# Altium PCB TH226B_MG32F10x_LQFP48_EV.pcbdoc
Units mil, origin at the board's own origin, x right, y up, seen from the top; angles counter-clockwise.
Board outline 3031.5 x 2165.35 mil, 2 copper layers (Top Layer, Bottom Layer); 46 components, 52 nets, 219 pads, 112 vias.
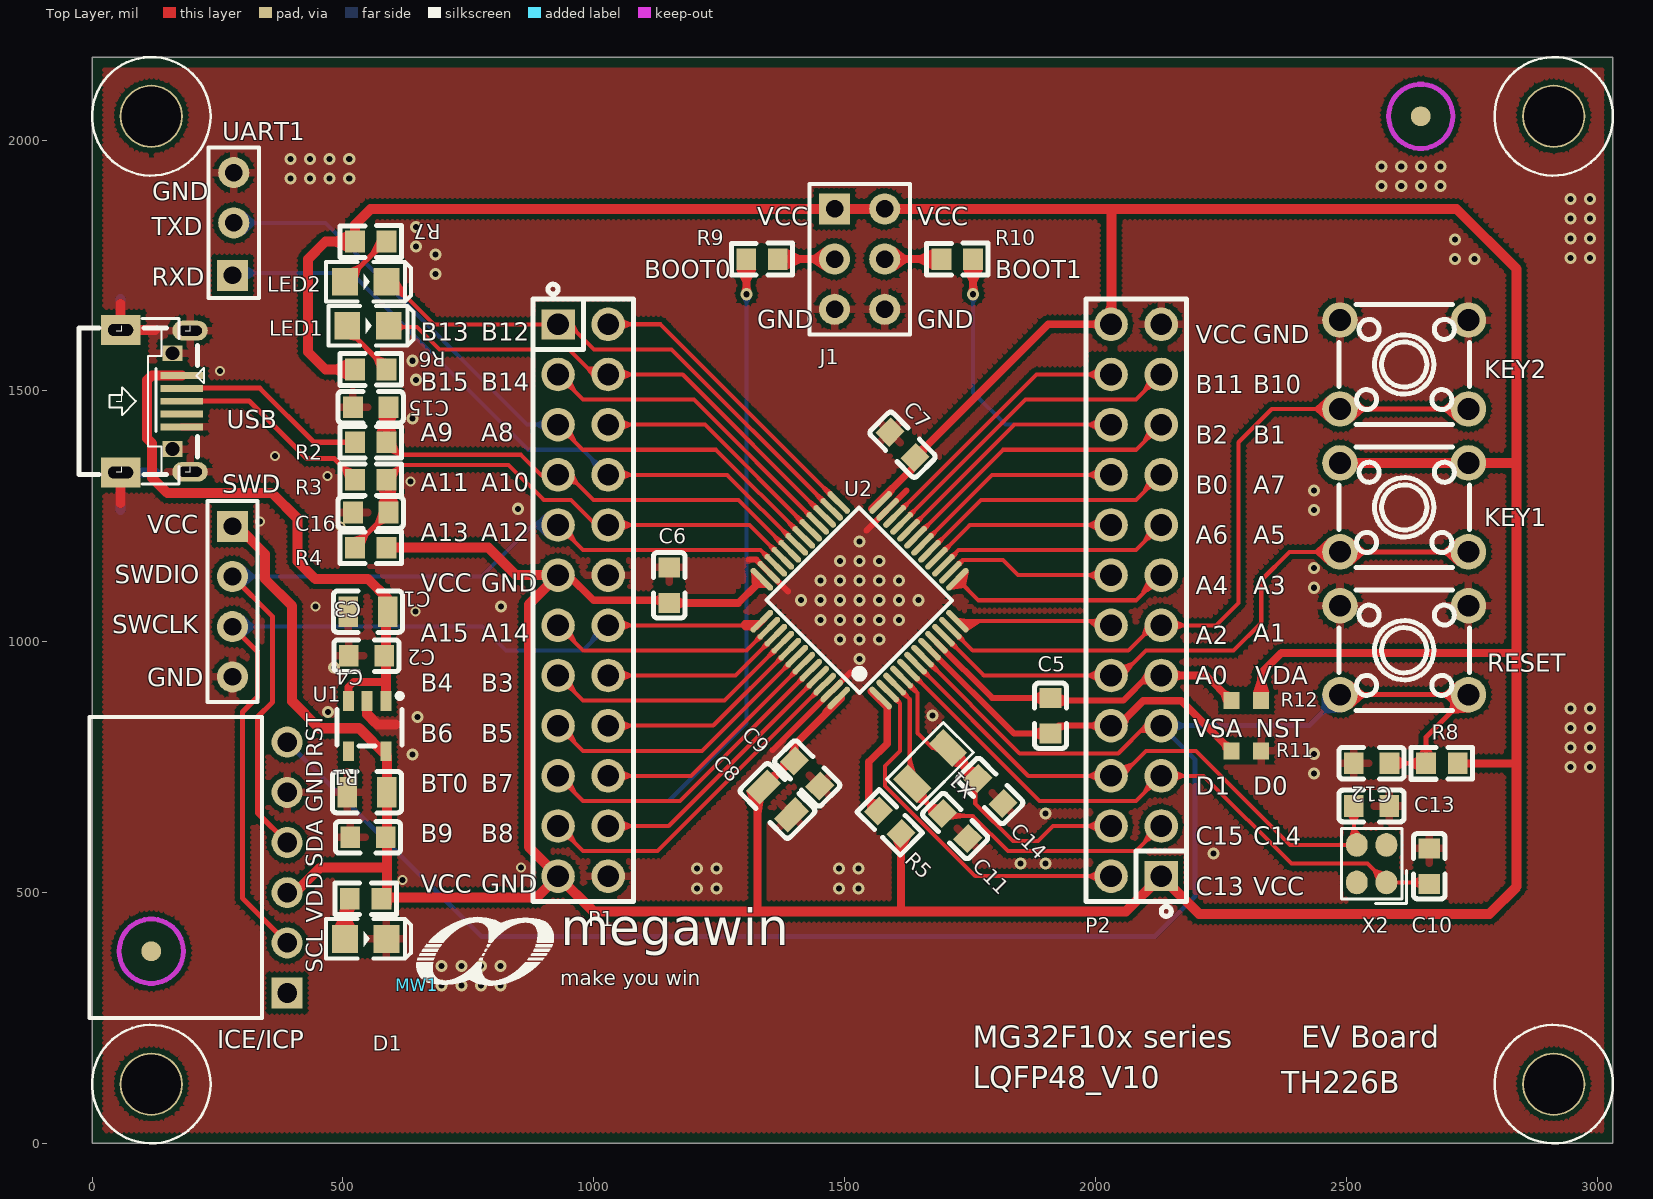
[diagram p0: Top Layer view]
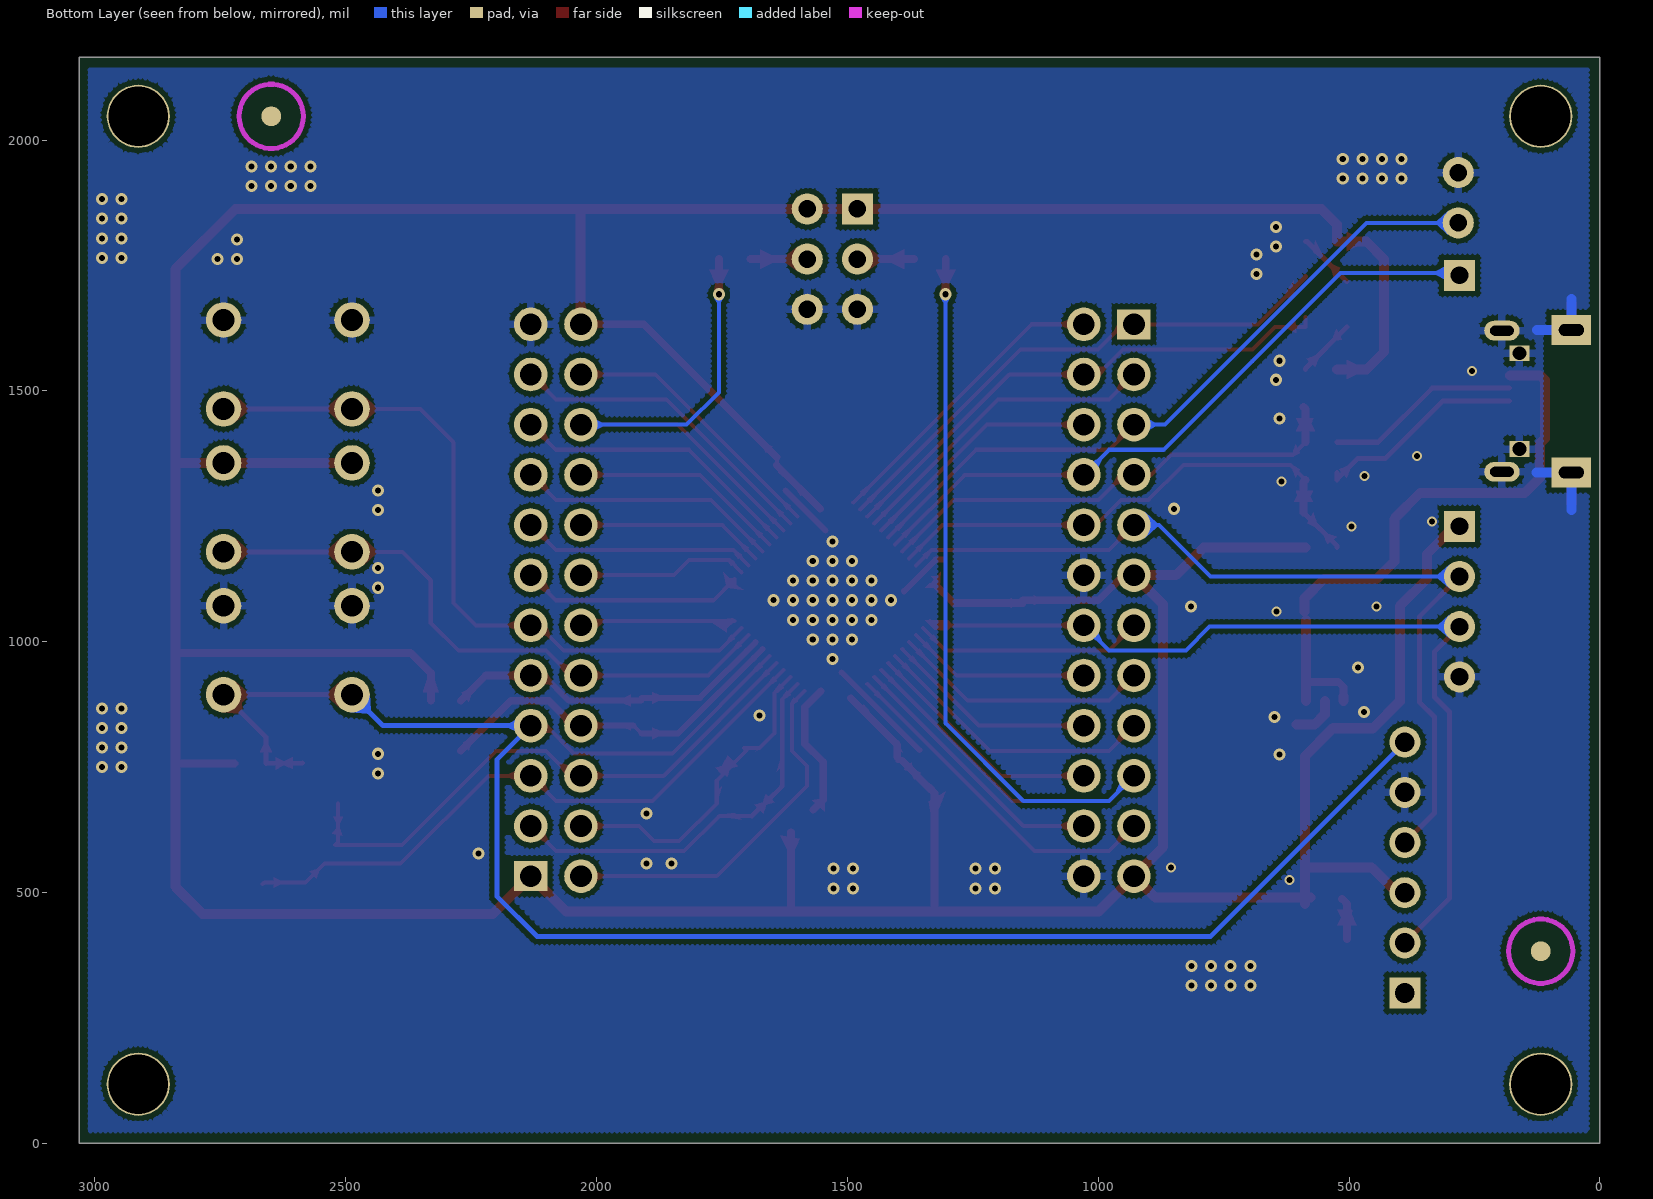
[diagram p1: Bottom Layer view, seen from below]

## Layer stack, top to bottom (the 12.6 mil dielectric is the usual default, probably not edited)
Top Layer: signal copper 1.4
Dielectric: dielectric 12.6, FR-4, Dk 4.8
Bottom Layer: signal copper 1.4

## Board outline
0,0 3031.5,0 3031.5,2165.35 0,2165.35

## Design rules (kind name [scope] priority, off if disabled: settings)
Clearance Clearance_1 [All] p1 off: gap=10
Clearance 6 [All] p2: gap=6
PolygonConnect via [isvia] p1: connectstyle=Direct reliefconductorwidth=10 reliefentries=4 polygonreliefangle="90 Angle"
PolygonConnect PolygonConnect_1 [All] p2: connectstyle=Relief reliefconductorwidth=15 reliefentries=4 polygonreliefangle="90 Angle"
RoomDefinition TH226B_MG32F10x_LQFP48_EV_V10 [InComponentClass('TH226B_MG32F10x_LQFP48_EV_V10')] p1: confinementstyle=ConfineIn formatcopy=TRUE lockcomponents=FALSE outline -125,-57 3071,-57 3071,2222 -125,2222
RoutingVias [All] p1: holewidth=28 width=50 viastyle="Through Hole" minholewidth=28 minwidth=50 maxholewidth=28 maxwidth=50
SilkscreenOverComponentPads SilkToSolderMaskClearance [IsPad] p1: minsilkscreentomaskgap=10
SolderMaskExpansion [All] p1: expansion=4
Width [All] p1: maxlimit=78.74 minlimit=5 preferedwidth=10
27 further rules are at their usual default settings.

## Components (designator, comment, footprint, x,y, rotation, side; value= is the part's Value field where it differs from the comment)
C1 "10uF" C0805 550,1059.78 r180 top
C2 "0.1uF" C0603 547.24,971.99 r180 top
C3 "10uF" C0805 548.3,700 r180 top
C4 "0.1uF" C0603 550,610 r180 top
C5 "0.1uF" C0603 1910.44,852.56 r270 top
C6 "0.1uF" C0603 1150.44,1112.56 r90 top
C7 "0.1uF" C0603 1615.44,1392.56 r135 top
C8 "10uF" C0805 1366.3,682.56 r315 top
C9 "0.1uF" C0603 1425.44,737.56 r315 top
C10 "20pF" C0603 2665.4,552.56 r90 top
C11 "12pF" C0603 1720.4,632.56 r315 top
C12 "0.1uF" C0603 2550.43,757.99 r180 top
C13 "20pF" C0603 2550.4,672.56 r0 top
C14 "12pF" C0603 1790.4,702.56 r315 top
C15 "20pF" C0603 555.44,1467.56 r0 top
C16 "20pF" C0603 555.44,1257.56 r0 top
D1 "" LED0805_RED 545.44,407.56 r0 top
ICE/ICP "" PS6P254F_90 388.94,299.78 r90 top locked (schematic designator J8)
J1 "CON3X2" HDR-M-2.54_2X3 1480,1862.56 r270 top
KEY1 "SW-PB4" KEY-TH_4P-L6.0-W6.0-P4.50-LS6.5 2615.43,1267.78 r180 top
KEY2 "SW-PB4" KEY-TH_4P-L6.0-W6.0-P4.50-LS6.5 2615.44,1552.56 r180 top
LED1 "" LED0805_RED 550,1630 r0 top
LED2 "" LED0805_GREEN 545.43,1717.56 r0 top
MW1 "MW-A4" MEGAWIN_3.4 648.48,315.01 r0 top (schematic designator IMPORTED_IMAGE)
P1 "CON12X2" HDR-TH_24P-P2.54-V-R2-C12-S2.54 978.87,1082.66 r270 top
P2 "CON12X2" HDR-TH_24P-P2.54-V-R2-C12-S2.54 2081.17,1082.66 r90 top
R1 "4.7k" R0603 545.4,487.56 r180 top
R2 "33" R0603 555.44,1397.56 r0 top
R3 "33" R0603 555.43,1322.56 r0 top
R4 "1.5k" R0603 555.44,1187.56 r0 top
R5 "0" R0603 1590,640 r135 top
R6 "1.5k" R0603 555.5,1542.56 r0 top
R7 "10k" R0603 555.5,1797.56 r0 top
R8 "10k" R0603 2690.44,757.56 r180 top
R9 "10k" R0603 1335.44,1762.56 r0 top
R10 "10k" R0603 1724.57,1762.56 r0 top
R11 "0" R0603-1 2300.44,782.56 r180 top
R12 "0" R0603-1 2300.44,882.56 r180 top
RESET "SW-PB4" KEY-TH_4P-L6.0-W6.0-P4.50-LS6.5 2615.43,982.99 r180 top
SWD "CON4" HDR-M-2.54_1X4 280,1080 r270 top
U1 "SPX3819M5-L-3-3" SOT-23-5_L3.0-W1.7-P0.95-LS2.8-TL 548.36,831.95 r180 top
U2 "MG32F10x" LQFP-48_L7.0-W7.0-P0.50-LS9.0-BL 1530,1082.68 r45 top
UART1 "CON3" HDR-M-2.54_1X3 282.5,1834.9 r90 top (schematic designator UART)
USB "MICRO_USB" USB5-micro_B-建倚MRUSB-5B-D17xx- 167.96,1479.36 r270 top
X1 "32.768MHz" OSC-SMD_L3.2-W1.5 1670.44,752.56 r45 top
X2 "12MHz" OSC-SMD_4P-L2.5-W2.0-BL 2550.44,557.56 r90 top

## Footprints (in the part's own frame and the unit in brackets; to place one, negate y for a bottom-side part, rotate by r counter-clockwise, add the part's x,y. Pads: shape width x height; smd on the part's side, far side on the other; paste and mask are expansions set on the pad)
C0603 [mm]
  rect 1x1.1 smd: 1(-0.9,0) 2(0.9,0)
  silkscreen extent -1.65,-0.8 1.65,0.8
C0805 [mm]
  rect 1x1.55 smd: 1(-1,0) 2(1,0)
  silkscreen extent -1.75,-1.04 1.75,1.04
HDR-M-2.54_1X3 [mil]
  rect 62x62 hole 35: 1(-104.9,2.5)
  round 62 hole 35: 2(0,0) 3(100,0)
  silkscreen extent -150,-50 150,50
HDR-M-2.54_1X4 [mil]
  rect 62x62 hole 35: 1(-150,0)
  round 62 hole 35: 2(-50,0) 3(50,0) 4(150,0)
  silkscreen extent -200,-50 200,50
HDR-M-2.54_2X3 [mil]
  rect 62x62 hole 35: 1(0,0)
  round 62 hole 35: 2(0,100) 3(100,0) 4(100,100) 5(200,0) 6(200,100)
  silkscreen extent -50,-50 250,150
HDR-TH_24P-P2.54-V-R2-C12-S2.54 [mm]
  rect 1.524x1.7 hole 1.1: 1(-13.97,-1.27)
  round 1.7 hole 1.1: 2(-13.97,1.27) 3(-11.43,-1.27) 4(-11.43,1.27) 5(-8.89,-1.27) 6(-8.89,1.27) 7(-6.35,-1.27) 8(-6.35,1.27) 9(-3.81,-1.27) 10(-3.81,1.27) 11(-1.27,-1.27) 12(-1.27,1.27) 13(1.27,-1.27) 14(1.27,1.27) 15(3.81,-1.27) 16(3.81,1.27) 17(6.35,-1.27) 18(6.35,1.27) 19(8.89,-1.27) 20(8.89,1.27) 21(11.43,-1.27) 22(11.43,1.27) 23(13.97,-1.27) 24(13.97,1.27)
  silkscreen extent -16,-2.54 15.24,2.54
KEY-TH_4P-L6.0-W6.0-P4.50-LS6.5 [mm]
  round 1.8 hole 1.1: 1(-3.251,-2.25) 2(3.251,-2.25) 3(3.251,2.25) 4(-3.251,2.25)
  silkscreen extent -3.3,-3.05 3.3,3.05
LED0805_GREEN [mil]
  rect 51.2x55.1 smd: 1(-41.35,0) 2(41.35,0)
  silkscreen extent -79,-39 91,39
LED0805_RED [mil]
  rect 51.2x55.1 smd: 1(-41.35,0) 2(41.35,0)
  silkscreen extent -79,-39 91,39
LQFP-48_L7.0-W7.0-P0.50-LS9.0-BL [mm]
  oval 0.3x1.5 smd: 1(-2.75,-4.25) 2(-2.25,-4.25) 3(-1.75,-4.25) 4(-1.25,-4.25) 5(-0.75,-4.25) 6(-0.25,-4.25) 7(0.25,-4.25) 8(0.75,-4.25) 9(1.25,-4.25) 10(1.75,-4.25) 11(2.25,-4.25) 12(2.75,-4.25) 25(2.75,4.25) 26(2.25,4.25) 27(1.75,4.25) 28(1.25,4.25) 29(0.75,4.25) 30(0.25,4.25) 31(-0.25,4.25) 32(-0.75,4.25) 33(-1.25,4.25) 34(-1.75,4.25) 35(-2.25,4.25) 36(-2.75,4.25)
  oval 1.5x0.3 smd: 13(4.25,-2.75) 14(4.25,-2.25) 15(4.25,-1.75) 16(4.25,-1.25) 17(4.25,-0.75) 18(4.25,-0.25) 19(4.25,0.25) 20(4.25,0.75) 21(4.25,1.25) 22(4.25,1.75) 23(4.25,2.25) 24(4.25,2.75) 37(-4.25,2.75) 38(-4.25,2.25) 39(-4.25,1.75) 40(-4.25,1.25) 41(-4.25,0.75) 42(-4.25,0.25) 43(-4.25,-0.25) 44(-4.25,-0.75) 45(-4.25,-1.25) 46(-4.25,-1.75) 47(-4.25,-2.25) 48(-4.25,-2.75)
  silkscreen extent -3.33,-3.31 3.3,3.34
MEGAWIN_3.4 [mil]
  silkscreen extent -2,0 272,135
OSC-SMD_4P-L2.5-W2.0-BL [mm]
  oval 1.2x1.1 smd: 1(-0.95,-0.75) 2(0.95,-0.75) 3(0.95,0.75) 4(-0.95,0.75)
  silkscreen extent -2.01,-1.76 1.78,1.53
OSC-SMD_L3.2-W1.5 [mm]
  rect 1.05x1.7 smd: 1(-1.275,0) 2(1.275,0)
  silkscreen extent -2.03,-1.08 2.03,1.08
PS6P254F_90 [mil]
  rect 62x62 hole 39.37: 1(0,0)
  round 62 hole 39.37: 2(100,0) 3(200,0) 4(300,0) 5(400,0) 6(500,0)
  silkscreen extent -50,50 550,394
R0603 [mm]
  rect 1x1.1 smd: 1(-0.8,0) 2(0.8,0)
  silkscreen extent -1.55,-0.8 1.55,0.81
R0603-1 [mil]
  rect 31.75x34.02 smd: 1(-29.66,0) 2(29.66,0)
SOT-23-5_L3.0-W1.7-P0.95-LS2.8-TL [mm]
  rect 0.55x1 smd: 1(-0.95,-1.271) 2(0,-1.271) 3(0.95,-1.271) 4(0.95,1.271) 5(-0.95,1.271)
  silkscreen extent -1.78,-1.65 1.52,1.02
USB5-micro_B-建倚MRUSB-5B-D17xx- [mm]
  rect 0.35x2.159 smd: 1(-1.3,0.279) 2(-0.65,0.279) 3(0,0.279) 4(0.65,0.279) 5(1.3,0.279)
  rect 0.8x1 hole 0.7: 5(-2.425,-0.19) 5(2.425,-0.19)
  oval 1x1.8 hole 0.5 slot 1.2 at 90 deg: 6(3.576,0.697) 9(-3.574,0.697)
  rect 1.5x2 hole 0.6 slot 1.27 at 90 deg: 7(3.607,-2.819) 8(-3.607,-2.819)
  silkscreen extent -4.19,-4.92 4.19,1.4, body extent -4,-5.61 4,-0.01, height 2.8

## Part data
C1 C2 C3 C4 C5 C6 C7 C8 C9 C10 C11 C12 C13 C14 C15 C16: library part CAP, "Capacitor"
D1 LED1 LED2: library part LED_SC
ICE/ICP: library part CON6, "Connector"
MW1: library part MW_A4
R1 R2 R3 R4 R5 R6 R7 R8 R9 R10 R11 R12: library part RES1
SWD UART1: "Connector"
U1: library part IC5_SPX3819M5-L-3-3
U2: library part IC48_MG32F10x
USB: library part USB_Micro
X1: library part XTAL, "Crystal"
X2: library part X3P_1, "Crystal"

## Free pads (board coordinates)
  round 125.98 hole 118.11: 0(118.11,118.12) 0(118.12,2047.25) 0(2913.38,118.11) 0(2913.39,2047.24)
  round 39.37 smd mask+39.37: 0(118.11,383.12) 0(2648.39,2047.24)
  round 39.37 smd far side mask+39.37: 0(118.11,383.12) 0(2648.39,2047.24)

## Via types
v1: diameter 24, hole 12, Top Layer to Bottom Layer, tented both sides, 102 vias
v2: diameter 20, hole 12, Top Layer to Bottom Layer, tented both sides, 10 vias

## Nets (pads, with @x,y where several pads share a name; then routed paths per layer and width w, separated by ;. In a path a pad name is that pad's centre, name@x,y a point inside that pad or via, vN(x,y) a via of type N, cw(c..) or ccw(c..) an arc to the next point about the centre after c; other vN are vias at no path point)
BOOT0: P1.19 R9.1 U2.44 | length 2018.2
  Top Layer w8.19: P1.19 978.97,682.56 1171.67,682.56 U2.44
  Top Layer w15.75: R9.1 v1(1304.57,1692.56)
  Bottom Layer w8.19: P1.19 978.97,682.56 1149.57,682.56 1304.57,837.56 v1(1304.57,1692.56)
D+: R3.1 USB.3 | length 444.8
  Top Layer w10: USB.3@180.2,1479.8 313.23,1479.8 428.03,1365 483.03,1365 R3.1@515.72,1332.31 ; 500.47,1347.56 R3.1@523.97,1324.06 ; R3.1 R3.1@523.97,1337.56
D-: R2.1 USB.2 | length 388.4
  Top Layer w10: USB.2@180.2,1505.4 334.6,1505.4 442.44,1397.56 R2.1
GND_POWER: C1.2 C2.2 C3.2 C4.2 C6.2 C7.2 C8.2 C9.2 C10.2 C11.2 C12.2 C13.2 C14.2 C15.1 C16.1 D1.2 ICE/ICP.5 J1.5 J1.6 KEY2.1 KEY2.2 P1.12 P1.24 P2.23 R11.1 RESET.1 RESET.2 SWD.4 U1.2 U2.23 U2.35 U2.47 UART1.3 USB.5 USB.6 USB.7 USB.8 USB.9 | length 981.2
  Top Layer w12: 1308.94,1163.46 1323.96,1163.46 1386.82,1100.58 ; 1356.79,784.23 1511.73,939.12 ; 1543.41,1221.37 1623.09,1301.02
  Top Layer w20: 56.96,1276.98 USB.7 ; 56.96,1673.02 USB.8 125.3,1621.36 ; U1.2 548.37,855.36 568.73,835 605,835
  Bottom Layer w20: 56.96,1263.02 USB.7 126.3,1337.36 ; 56.96,1682.82 USB.8 125.3,1621.36
  other v1: 696.96,314.78 736.06,314.78 775.15,314.78 814.25,314.78 696.96,353.87 736.06,353.87 775.15,353.87 814.25,353.87 1205.44,508.47 1244.53,508.47 1488.63,508.47 1527.72,508.47 1205.44,547.56 1244.53,547.56 1488.63,547.56 1527.72,547.56 1850.44,557.56 1900.44,557.56 2235.46,577.56 1900.44,657.56 2435.46,737.56 2946.57,749.9 2985.67,749.9 638.94,775 2435.46,776.66 2946.57,788.99 2985.67,788.99 2946.57,828.09 2985.67,828.09 648.94,850 1675.46,852.56 470,860 2946.57,867.18 2985.67,867.18 482.28,948.37 1530,965.41 1490.91,1004.5 1530,1004.5 1569.09,1004.5 1451.82,1043.59 1490.91,1043.59 1530,1043.59 1569.09,1043.59 1608.19,1043.59 815,1069.78 1412.73,1082.68 1451.82,1082.68 1490.91,1082.68 1530,1082.68 1569.09,1082.68 1608.19,1082.68 1647.28,1082.68 2435.46,1107.56 1451.82,1121.77 1490.91,1121.77 1530,1121.77 1569.09,1121.77 1608.19,1121.77 2435.46,1146.66 1490.91,1160.86 1530,1160.86 1569.09,1160.86 1530,1199.95 2435.46,1262.56 848.94,1265 2435.46,1301.66 638.94,1445 645.46,1522.12 638.94,1560 684.55,1732.56 2716.37,1762.56 2755.46,1762.56 2946.57,1764.9 2985.67,1764.9 684.55,1771.66 645.46,1787.56 2716.37,1801.66 2946.57,1803.99 2985.67,1803.99 645.46,1826.66 2946.57,1843.09 2985.67,1843.09 2946.57,1882.18 2985.67,1882.18 2570.44,1908.46 2609.53,1908.46 2648.63,1908.46 2687.72,1908.46 395.44,1923.46 434.53,1923.46 473.63,1923.46 512.72,1923.46 2570.44,1947.56 2609.53,1947.56 2648.63,1947.56 2687.72,1947.56 395.44,1962.56 434.53,1962.56 473.63,1962.56 512.72,1962.56
  other v2: 618.94,525 855,549.78 645,1059.78 445,1069.78 495,1229.78 335,1239.78 635,1319.78 468.94,1330 365,1369.78 255,1539.78
NetD1_1: D1.1 R1.2 | length 84.1
  Top Layer w15.75: D1.1 504.07,477.66 R1.2
NetJ1_3: J1.3 R9.2 | length 113
  Top Layer w15.75: R9.2 J1.3@1479.97,1762.56
NetJ1_4: J1.4 R10.1 | length 113.1
  Top Layer w15.75: J1.4@1579.97,1762.56 R10.1
NetLED1_1: LED1.1 R6.2 | length 119.3
  Top Layer w10: LED1.1@504.07,1627.56 586.97,1544.66 R6.2
NetLED2_1: LED2.1 R7.2 | length 116
  Top Layer w10: LED2.1 584.07,1797.56 R7.2
NRST: C12.1 ICE/ICP.6 P2.7 R8.2 RESET.3 RESET.4 U2.7 | length 4043.2
  Top Layer w8.19: U2.7@1655.27,971.36 1849.07,777.56 2045.47,777.56 2100.57,832.66 P2.7
  Top Layer w10: RESET.3 RESET.4 2658.97,809.86 R8.2 C12.1
  Bottom Layer w10: ICE/ICP.6 776.07,412.66 1888.87,412.66 ; 2098.87,412.66 1888.87,412.66 ; RESET.3 2425.67,832.66 P2.7 2198.87,764.96 2198.87,492.66 2118.87,412.66 1888.87,412.66
PA0: KEY1.3 KEY1.4 P2.10 U2.10 | length 1231.6
  Top Layer w8.19: U2.10 1777.47,932.66 P2.10 2050.57,932.66 2100.47,982.56 2275.47,982.56 2330.47,1037.56 2330.47,1122.56 2387.07,1179.16 KEY1.3
  Top Layer w10: KEY1.3 KEY1.4
PA1: KEY2.3 KEY2.4 P2.11 U2.11 | length 1437.6
  Top Layer w8.19: U2.11 1755.37,982.56 2065.47,982.56 2115.57,1032.66 P2.11 2240.57,1032.66 2285.47,1077.56 2285.47,1397.56 2351.37,1463.56 KEY2.3
  Top Layer w10: KEY2.3 KEY2.4
PA2: P2.12 U2.12 | length 309.8
  Top Layer w8.19: U2.12@1724.87,1040.96 2022.97,1040.96 P2.12
PA3: P2.13 U2.13 | length 444.4
  Top Layer w8.19: U2.13@1724.87,1124.46 1766.77,1082.56 2081.07,1082.56 P2.13
PA4: P2.14 U2.14 | length 342.6
  Top Layer w8.19: U2.14 1735.17,1162.56 1815.47,1162.56 1845.37,1132.66 P2.14
PA5: P2.15 U2.15 | length 467.4
  Top Layer w8.19: U2.15 1727.37,1182.56 2081.07,1182.56 P2.15
PA6: P2.16 U2.16 | length 375.6
  Top Layer w8.19: U2.16@1683.07,1166.16 1749.57,1232.66 P2.16
PA7: P2.17 U2.17 | length 525.2
  Top Layer w8.19: U2.17@1669.17,1180.06 1771.67,1282.56 2081.07,1282.56 P2.17
PA8: P1.6 U2.29 | length 491
  Top Layer w8.19: P1.6 1221.77,1432.66 U2.29
PA9: P1.5 U2.30 UART1.2 | length 1395.9
  Top Layer w8.19: P1.5 978.97,1382.56 1244.07,1382.56 U2.30
  Bottom Layer w8.19: UART1.2 465.1,1834.9 867.34,1432.66 P1.5
PA10: P1.8 U2.31 UART1.1 | length 1358.5
  Top Layer w8.19: P1.8 1266.07,1332.66 U2.31@1404.77,1194.06
  Bottom Layer w8.19: UART1.1@282.5,1734.9 517.23,1734.9 693.19,1558.94 ; 684.57,1567.56 869.57,1382.56 978.97,1382.56 P1.8
PA11: C15.2 P1.7 R2.2 U2.32 | length 1000.8
  Top Layer w8.19: P1.7@928.77,1332.66 895.07,1332.66 855.17,1372.56 611.97,1372.56 ; P1.7 949.47,1332.66 999.57,1282.56 1288.27,1282.56 U2.32@1390.77,1180.06 ; 611.97,1372.56 R2.2 611.93,1372.56
  Top Layer w15.75: R2.2 586.97,1463.66 C15.2
PA12: C16.2 P1.10 R3.2 R4.1 U2.33 | length 1065.1
  Top Layer w8.19: R3.2@601.97,1337.56 R3.2 616.97,1352.56 830.44,1352.56 900.44,1282.56 954.57,1282.56 1004.47,1232.66 P1.10 1310.37,1232.66 U2.33@1376.87,1166.16
  Top Layer w10: R4.1 523.97,1190.66 C16.2
  Top Layer w15.75: R3.2 590.87,1318.66 C16.2
PA13: ICE/ICP.4 P1.9 SWD.2 U2.34 | length 1768.9
  Top Layer w8.19: P1.9 978.97,1182.56 1332.67,1182.56 U2.34
  Top Layer w10: SWD.2 360,1050 360,880 330,850 330,658.73 ICE/ICP.4
  Bottom Layer w8.19: SWD.2@270,1130 SWD.2 776.21,1130 878.87,1232.66 P1.9@928.77,1232.66
PA14: ICE/ICP.2 P1.14 SWD.3 U2.37 | length 1794.6
  Top Layer w8.19: P1.14 1326.87,1032.66 U2.37@1335.17,1040.96
  Top Layer w10: SWD.3 330,980 330,890 300,860 300,488.73 ICE/ICP.2@385.76,402.97
  Bottom Layer w8.19: SWD.3 778.03,1030 825.47,982.56 978.67,982.56 P1.14@1028.77,1032.66
PA15: P1.13 U2.38 | length 459.3
  Top Layer w8.19: P1.13 978.97,982.56 1304.57,982.56 U2.38
PB0: P2.18 U2.18 | length 433.3
  Top Layer w8.19: U2.18@1655.27,1194.06 1793.97,1332.66 P2.18
PB1: P2.19 U2.19 | length 582.9
  Top Layer w8.19: U2.19 1815.97,1382.56 2081.07,1382.56 P2.19
PB2: P2.20 R10.2 U2.20 | length 1058.4
  Top Layer w8.19: U2.20 1838.27,1432.66 P2.20
  Top Layer w15.75: v1(1756.06,1692.56) R10.2
  Bottom Layer w8.19: v1(1756.06,1692.56) 1756.07,1496.96 1820.37,1432.66 P2.20
PB3: P1.16 U2.39 | length 367.4
  Top Layer w8.19: P1.16 1282.57,932.66 U2.39
PB4: P1.15 U2.40 | length 517
  Top Layer w8.19: P1.15 978.97,882.56 1260.27,882.56 U2.40
PB5: P1.18 U2.41 | length 425.1
  Top Layer w8.19: P1.18 1238.27,832.66 U2.41@1390.77,985.26
PB6: P1.17 U2.42 | length 574.9
  Top Layer w8.19: P1.17 978.97,782.56 1215.97,782.56 U2.42@1404.77,971.36
PB7: P1.20 U2.43 | length 482.9
  Top Layer w8.19: P1.20 1193.97,732.66 U2.43
PB8: P1.22 U2.45 | length 540.6
  Top Layer w8.19: P1.22 1149.57,632.66 U2.45
PB9: P1.21 U2.46 | length 690.3
  Top Layer w8.19: P1.21 978.97,582.56 1127.37,582.56 U2.46@1460.37,915.66
PB10: P2.21 U2.21 | length 640.6
  Top Layer w8.19: U2.21 1860.37,1482.56 2081.07,1482.56 P2.21
PB11: P2.22 U2.22 | length 548.8
  Top Layer w8.19: U2.22@1599.57,1249.76 1882.57,1532.66 P2.22
PB12: P1.2 U2.25 | length 606.5
  Top Layer w8.19: P1.2 1133.07,1632.66 U2.25
PB13: LED2.2 P1.1 U2.26 | length 1080.2
  Top Layer w8: 616.26,1698.12 681.72,1632.66 P1.1@928.77,1632.66
  Top Layer w8.19: P1.1 950.37,1632.66 1000.47,1582.56 1155.37,1582.56 U2.26@1474.37,1263.66
  Top Layer w10: LED2.2@586.82,1727.56 616.72,1697.66
PB14: LED1.2 P1.4 U2.27 | length 1050
  Top Layer w8.19: LED1.2@586.79,1647.56 586.79,1627.56 647.44,1627.56 692.44,1582.56 950.47,1582.56 1000.27,1532.66 P1.4@1028.77,1532.66 ; P1.4 1177.47,1532.66 U2.27@1460.37,1249.76
PB15: P1.3 U2.28 | length 640.6
  Top Layer w8.19: P1.3 978.97,1482.56 1199.67,1482.56 U2.28
PC13: P2.2 U2.2 | length 737.1
  Top Layer w8.19: U2.2@1585.67,901.76 1610.47,876.96 1610.47,782.56 1580.47,752.56 1580.47,712.56 1760.37,532.66 P2.2
PC14: C11.1 P2.3 U2.3 X1.1 | length 791.5
  Top Layer w8.19: U2.3 1629.97,885.26 X1.1@1629.97,712.06 ; C11.1@1690.37,652.66 1755.37,652.66 1825.47,582.56 2081.07,582.56 P2.3
  Top Layer w10: X1.1@1629.97,712.06 C11.1@1690.37,652.66
PC15: C14.1 P2.4 U2.4 X1.2 | length 648.5
  Top Layer w8.19: U2.4 1645.47,897.66 1645.47,817.56 ; 1646.07,816.96 1674.97,788.06 X1.2 1700.97,783.06 1760.37,723.56 1760.37,677.66 1835.47,602.56 1885.47,602.56 1915.47,632.56 P2.4
PD0: C10.1 P2.5 U2.5 X2.1 | length 1256
  Top Layer w8.19: U2.5 1888.37,682.56 2081.07,682.56 P2.5 2215.37,732.66 2390.47,557.56 2542.57,557.56 X2.1 2662.37,520.16 C10.1@2665.37,517.16
PD1: C13.1 P2.6 U2.6 X2.3 | length 1156
  Top Layer w8.19: U2.6 1866.07,732.66 P2.6 2050.57,732.66 2100.47,782.56 2200.47,782.56 2388.07,594.96 2520.87,594.96 2514.97,600.86 C13.1@2514.97,677.56
VBAT: R5.2 U2.1 | length 301.3
  Top Layer w8.19: 1548.17,684.86 R5.2@1568.17,664.86
  Top Layer w15: U2.1@1553.4,901.19 1585.04,869.52 1585,797.04 1548.17,760.26 1548.17,684.82 R5.2@1568.17,664.83
VCC: C3.1 C4.1 C6.1 C7.1 C8.1 C9.1 ICE/ICP.3 J1.1 J1.2 KEY1.1 KEY1.2 P1.11 P1.23 P2.1 P2.24 R1.1 R4.2 R5.1 R6.1 R7.1 R8.1 R12.1 SWD.1 U1.5 U2.24 U2.36 U2.48 | length 11640.7
  Top Layer w8.19: C6.1@1150.47,1077.16 C6.1@1150.47,1082.56 ; C9.1@1390.67,762.56 C9.1 1400.37,799.96 ; C7.1@1640.47,1346.26 C7.1@1640.47,1367.56
  Top Layer w15: P1.11@949.47,1132.66 999.57,1082.56 C6.1@1150.44,1082.56 ; C6.1@1150.47,1077.16 1287.87,1077.16 1325.62,1114.9 ; C8.1 C9.1@1390.67,762.56 ; C9.1@1400.37,770 1400.38,794.98 U2.48@1493.27,887.76 ; U2.24@1554.61,1265.39 C7.1@1640.47,1351.26 ; C7.1@1640.47,1367.56 1905.67,1632.66 P2.24
  Top Layer w15.75: SWD.1@280.03,1220 SWD.1 ; 1326.07,462.56 1326.07,697.96 C8.1 ; 1612.67,462.56 R5.1@1612.67,620.26 ; R12.1 2330.07,937.26 2370.47,977.56 2839.57,977.56 ; R8.1 2839.57,757.56
  Top Layer w20: SWD.1 290,1230 345,1175 345,1125 398.87,1071.13 398.87,881.13 452.44,827.56 532.44,827.56 587.67,772.33 587.67,550 ; ICE/ICP.3 404.78,499.78 455,550 587.67,550 ; R6.1@523.97,1542.56 465.47,1542.56 430.47,1577.56 430.47,1762.56 465.47,1797.56 523.97,1797.56 523.97,1831.06 555.46,1862.56 J1.1 J1.2 2031.57,1862.56 ; R1.1@576.89,490 886.21,490 P1.23 ; R4.2 790,1187.56 844.9,1132.66 P1.11 870.53,1074.32 870.53,590.99 P1.23 ; R1.1@587.67,476.78 587.67,550 ; P2.24@2031.57,1633.06 2031.57,1862.56 ; KEY1.2 2839.57,1356.37 ; P1.23 998.97,462.56 1326.07,462.56 1612.67,462.56 2061.07,462.56 P2.1 2206.27,457.56 2785.47,457.56 2839.57,511.66 2839.57,757.56 2839.57,977.56 2839.57,1356.37 ; 2031.57,1862.56 2719.67,1862.56 2839.57,1742.66 2839.57,1356.37
VCC5: C1.1 C2.1 U1.1 U1.3 USB.1 | length 1204
  Top Layer w15.75: USB.1@178.96,1530.9 USB.1@180.2,1530.9 ; U1.3@510.96,891.35 510.87,882.06 510.87,909.29 521.64,920.06 585.41,920.06
  Top Layer w20: USB.1@178.96,1530.9 119.4,1530.9 110,1521.5 110,1405 120,1395 120,1326.5 150,1296.5 358.5,1296.5 410,1245 410,1160 445,1125 550,1125 589.37,1085.63 C1.1 ; U1.3 U1.3@510.96,891.35 ; U1.1 C1.1@585.77,1043.1
VDDA: C5.1 P2.9 R12.2 U2.9 | length 680.7
  Top Layer w10: C5.1@1910.47,882.56 C5.1 ; P2.9@2105.57,932.66 P2.9
  Top Layer w12: U2.9@1683.07,999.16 1794.27,887.96 C5.1 ; C5.1@1910.47,882.56 2055.47,882.56 P2.9@2105.57,932.66
  Top Layer w15: P2.9 2220.67,932.66 R12.2
VSSA: C5.2 P2.8 R11.2 U2.8 | length 739.8
  Top Layer w8.19: C5.2 C5.2@1926,832.68
  Top Layer w12: U2.8@1669.17,985.26 1837.37,817.16 C5.2@1910.47,817.16 ; C5.2@1926,832.68 P2.8@2045.59,832.68
  Top Layer w15: P2.8@2045.59,832.68 2095.47,882.56 2170.78,882.56 R11.2
pads on no net: ICE/ICP.1 U1.4 USB.4 X2.2 X2.4

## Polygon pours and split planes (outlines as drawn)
GND_POWER on Bottom Layer "Top Layer-GND" (hatched 90Degree grid 10 track 10, remove dead copper, pour order 0): 25,2140 3010,2140 3010,25 25,25
GND_POWER on Top Layer "Top Layer-GND" (hatched 90Degree grid 10 track 10, remove dead copper, pour order 0): 25,2140 3010,2140 3010,25 25,25

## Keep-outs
Top Layer:
  circle w10: c118.11,383.12 r64.06
  circle w10: c2648.39,2047.24 r64.06
Bottom Layer:
  circle w10: c118.11,383.12 r64.06
  circle w10: c2648.39,2047.24 r64.06

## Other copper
Top Layer:
  pour cut-out: -5.06,1337.32 116.78,1337.32 116.78,1619.91 -4.69,1619.91
  region net D+: 504.26,1325.46 520.8,1344.21 505.52,1349.57 498.9,1342.06
  region net PC14: 2123.71,614.96 2103.72,619.37 2095.4,602.68 2106.98,602.68
  region net PC14: 1724.61,659.01 1711.03,645.42 1731.54,648.56 1739.73,656.75
  region net VCC: 1172.09,1087.39 1172.09,1066.92 1184.37,1073.06 1184.37,1081.25
  region net VCC: 1338.2,1113.01 1323.72,1127.48 1319.38,1114.46 1325.17,1108.66
  region net VCC: 1320.46,1117.56 1320.46,1112.56 1315.46,1107.56 1314.06,1138.96 1322.19,1130.83 1333.73,1130.83
  region net VCC: 1320.46,1112.56 1320.46,1107.56 1346.56,1106.46 1336.56,1116.46 1331.56,1116.46
  region net PA3: 1735.46,1112.56 1740.46,1107.56 1705.46,1102.56 1721.73,1113.82 1721.73,1126.27
  region net PA3: 1740.46,1107.56 1747.31,1139.4 1734.18,1126.27 1721.73,1126.27 1725.46,1122.56
  region net PA3: 2125.95,1114.96 2101.79,1121.36 2091.38,1099.96 2105.52,1099.96
  region net PA4: 2000.97,1122.43 2000.95,1142.9 1988.67,1136.75 1988.68,1128.56
  region net PA4: 1731.82,1150.88 1723.48,1159.24 1732.28,1165.46 1738.06,1159.66
  region net PA11: 606.62,1394.27 597.58,1375.9 608.48,1370.23 612.3,1377.99
  region net PA11: 898.61,1322.44 898.61,1342.91 895.07,1336.77 895.07,1328.58
  region net PA11: 606.62,1445.9 571.18,1445.9 579.06,1422.28 594.81,1422.28
  region net PA11: 567.25,1419.21 606.62,1419.21 594.81,1442.83 579.06,1442.83
  region net PA5: 2123.71,1214.96 2103.72,1219.37 2095.4,1202.68 2106.98,1202.68
  region net PA5: 1717.91,1164.79 1709.58,1173.16 1719.56,1180.54 1725.34,1174.73
  region net VCC: 1128.78,1072.32 1128.78,1092.79 1116.5,1086.65 1116.5,1078.46
  region net PA13: 956.32,1219.41 936.33,1214.96 953.06,1202.68 964.64,1202.68
  region net PA13: 1350.44,1173.15 1342.1,1164.79 1334.68,1174.75 1340.47,1180.55
  region net VDDA: 2110.91,915.54 2098.27,937.11 2089.04,923.19 2094.26,914.28
  region net VDDA: 1932.09,895.06 1932.09,870.06 1947.09,877.56 1947.09,887.56
  region net NRST: 2646.47,779.21 2671.47,779.21 2663.97,794.21 2653.97,794.21
  region net NRST: 2708.07,896.57 2745.69,859.03 2712.9,856.71 2705.82,863.77
  region net PB13: 610,1720 608.96,1691.13 622.57,1684.73 627.69,1693.76
  region net VDDA: 2254.91,879.29 2269.54,899.56 2255.15,905.25 2249.22,897.04
  region net VDDA: 2159.48,945.17 2159.46,920.17 2174.47,927.66 2174.48,937.66
  region net VSSA: 2000.96,822.44 2000.96,842.91 1988.68,836.77 1988.68,828.58
  region net VSSA: 1932.09,836.8 1932.09,822.44 1944.37,828.58 1944.37,836.77
  region net VSSA: 2064.27,836.28 2049.29,850.23 2062.16,855.03 2068.15,849.45
  region net VSSA: 2254.91,782.58 2266.33,799.56 2254.76,804.37 2250.1,797.44
  region net PA12: 597.56,1344.21 606.62,1325.85 612.29,1342.12 608.46,1349.88
  region net PA12: 583.46,1235.9 571.19,1257.69 564.77,1238.53 569.86,1229.48
  region net PA12: 523.55,1209.26 543.6,1194.33 549.22,1208.84 541.12,1214.88
  region net PD1: 2499.25,592.99 2499.25,596.92 2486.97,599.05 2486.97,590.86
  region net PD1: 2046.92,750.39 2046.92,714.96 2072.99,749.29 2070.88,758.75
  region net PC15: 1717.36,752.15 1731.83,766.63 1736.18,753.6 1730.39,747.81
  region net PC15: 1739.72,729.79 1754.2,744.27 1741.17,748.61 1735.38,742.82
  region net PC15: 1764.9,699.29 1749.55,712.83 1756.28,690.51 1764.47,683.29
  region net PC15: 2000.98,622.41 2000.94,642.88 1988.67,636.72 1988.68,628.53
  region net PC15: 1749.21,734.3 1763.69,748.77 1750.66,753.12 1744.87,747.33
  region net PC15: 1724.36,759.15 1738.84,773.62 1756.45,741.54 1735.38,742.82
  region net PC15: 2000.98,622.41 2000.94,642.88 1988.67,636.72 1988.68,628.53
  region net VCC: 1475.72,866.93 1467.37,875.28 1455.79,861.14 1461.58,855.35
  region net PB9: 1447.87,894.75 1439.54,903.12 1432.11,893.18 1437.88,887.37
  region net PB8: 1433.96,908.69 1425.61,917.04 1418.2,907.08 1423.99,901.29
  region net BOOT0: 1420.05,922.6 1411.69,930.95 1404.29,920.97 1410.09,915.19
  region net PB7: 1406.14,936.55 1397.76,944.86 1390.39,934.87 1396.2,929.1
  region net PB6: 1392.2,950.44 1383.85,958.79 1376.45,948.82 1382.24,943.03
  region net PB5: 1378.27,964.36 1369.94,972.73 1362.51,962.77 1368.29,956.97
  region net PB4: 1364.36,978.28 1356.01,986.63 1344.42,972.5 1350.21,966.71
  region net PB3: 1350.45,992.2 1342.09,1000.55 1334.69,990.57 1340.49,984.79
  region net PA15: 1336.52,1006.12 1328.17,1014.47 1320.77,1004.5 1326.56,998.71
  region net PA12: 1364.35,1187.08 1356.02,1178.7 1348.59,1188.65 1354.36,1194.45
  region net PA11: 1369.93,1192.63 1378.28,1200.99 1364.1,1212.52 1358.31,1206.73
  region net PA10: 1383.85,1206.56 1392.2,1214.91 1378.08,1226.51 1372.29,1220.72
  region net PA9: 1397.77,1220.47 1406.12,1228.83 1392,1240.42 1386.21,1234.63
  region net PA8: 1411.69,1234.39 1420.04,1242.75 1405.9,1254.32 1400.1,1248.53
  region net PB15: 1433.95,1256.68 1425.62,1248.3 1418.19,1258.25 1423.96,1264.06
  region net PB14: 1439.53,1262.23 1447.88,1270.59 1433.75,1282.17 1427.96,1276.38
  region net PB13: 1453.45,1276.15 1461.8,1284.51 1447.69,1296.12 1441.9,1290.33
  region net PB12: 1467.37,1290.07 1475.72,1298.42 1461.59,1310.02 1455.8,1304.23
  region net VCC: 1592.64,1290.07 1584.29,1298.43 1594.25,1305.83 1600.04,1300.04
  region net PB11: 1620.5,1262.25 1612.11,1270.57 1622.05,1278.01 1627.86,1272.25
  region net PB10: 1634.38,1248.3 1626.07,1256.69 1636.07,1264.05 1641.83,1258.23
  region net PB2: 1648.31,1234.39 1639.98,1242.76 1649.96,1250.14 1655.74,1244.33
  region net PB1: 1662.24,1220.47 1653.89,1228.83 1663.85,1236.23 1669.64,1230.44
  region net PB0: 1676.15,1206.56 1667.79,1214.9 1677.76,1222.32 1683.55,1216.53
  region net PA7: 1690.07,1192.63 1681.73,1200.99 1691.71,1208.38 1697.49,1202.59
  region net PA6: 1703.99,1178.72 1695.64,1187.06 1705.6,1194.47 1711.39,1188.69
  region net PA2: 1725.95,1048.2 1740.43,1033.72 1754.66,1036.86 1746.47,1045.05
  region net PA1: 1731.83,1014.47 1723.47,1006.12 1733.43,998.71 1739.23,1004.49
  region net PA0: 1717.92,1000.55 1709.57,992.2 1719.54,984.8 1725.33,990.59
  region net VDDA: 1703.99,986.63 1695.64,978.28 1706.88,968.31 1713.96,975.38
  region net VSSA: 1690.08,972.72 1681.73,964.37 1692.97,954.4 1700.05,961.47
  region net NRST: 1676.15,958.79 1667.8,950.44 1681.96,938.88 1687.75,944.67
  region net PD1: 1662.25,944.87 1653.88,936.54 1663.83,929.11 1669.63,934.89
  region net PD0: 1648.32,930.95 1639.97,922.6 1649.94,915.2 1655.73,920.99
  region net PC15: 1634.4,917.04 1626.05,908.69 1640.21,897.13 1646,902.92
  region net PC14: 1620.48,903.11 1612.13,894.76 1622.09,887.35 1627.88,893.14
  region net PC13: 1606.55,889.2 1598.21,880.84 1607.58,874.06 1613.36,879.86
  region net VCC: 2015.42,1650.39 2046.92,1650.39 2039.12,1674.02 2023.37,1674.02
  region net VCC: 2000.96,1622.44 2000.96,1642.91 1988.68,1636.77 1988.68,1628.58
  region net PB11: 2000.97,1522.43 2000.95,1542.9 1988.67,1536.75 1988.68,1528.56
  region net PB10: 2123.71,1514.96 2103.72,1519.37 2095.4,1502.68 2106.98,1502.68
  region net PB2: 2000.97,1422.43 2000.95,1442.9 1988.67,1436.75 1988.68,1428.56
  region net PB1: 2123.71,1414.96 2103.72,1419.37 2095.4,1402.68 2106.98,1402.68
  region net PB0: 2000.97,1322.43 2000.95,1342.9 1988.67,1336.75 1988.68,1328.56
  region net PA7: 2123.71,1314.96 2103.72,1319.37 2095.4,1302.68 2106.98,1302.68
  region net PA6: 2000.97,1222.43 2000.95,1242.9 1988.67,1236.75 1988.68,1228.56
  region net PA2: 2004.84,1046.89 1998.5,1027.42 1988.66,1036.86 1991.32,1045.05
  region net PA1: 2161.39,1042.9 2161.37,1022.43 2173.66,1028.56 2173.67,1036.75
  region net PA1: 2112.51,1015.2 2097.97,1029.61 2093.69,1016.56 2099.5,1010.8
  region net PA0: 2000.97,922.43 2000.95,942.9 1988.67,936.75 1988.68,928.56
  region net PA0: 2046.92,950.39 2046.92,914.96 2072.99,949.29 2070.88,958.75
  region net NRST: 2105.82,817.78 2098.18,836.78 2088.95,826.82 2092.27,818.57
  region net PD1: 2000.97,722.43 2000.95,742.9 1988.67,736.75 1988.68,728.56
  region net PD0: 2123.71,714.96 2103.72,719.37 2095.4,702.68 2106.98,702.68
  region net PD0: 2161.39,742.9 2161.37,722.43 2173.66,728.56 2173.67,736.75
  region net PC13: 2000.97,522.43 2000.95,542.9 1988.67,536.75 1988.68,528.56
  region net PB8: 1059.04,642.9 1059.02,622.43 1071.31,628.56 1071.32,636.75
  region net PB9: 956.31,619.41 936.33,614.96 953.06,602.68 964.64,602.68
  region net PB7: 1059.04,742.9 1059.02,722.43 1071.31,728.56 1071.32,736.75
  region net BOOT0: 956.31,719.41 936.33,714.96 953.06,702.68 964.64,702.68
  region net PB5: 1059.04,842.9 1059.02,822.43 1071.31,828.56 1071.32,836.75
  region net PB6: 956.31,819.41 936.33,814.96 953.06,802.68 964.64,802.68
  region net PB3: 1059.04,942.9 1059.02,922.43 1071.31,928.56 1071.32,936.75
  region net PB4: 956.31,919.41 936.33,914.96 953.06,902.68 964.64,902.68
  region net PA14: 1059.04,1042.9 1059.02,1022.43 1071.31,1028.56 1071.32,1036.75
  region net PA15: 956.31,1019.41 936.33,1014.96 953.06,1002.68 964.64,1002.68
  region net PA12: 1059.04,1242.9 1059.02,1222.43 1071.31,1228.56 1071.32,1236.75
  region net PA10: 1059.04,1342.9 1059.02,1322.43 1071.31,1328.56 1071.32,1336.75
  region net PA11: 962.27,1331.97 949.79,1315.75 963.25,1313.09 968.28,1319.64
  region net PA8: 1059.04,1442.9 1059.02,1422.43 1071.31,1428.56 1071.32,1436.75
  region net PA9: 956.31,1419.41 936.33,1414.96 953.06,1402.68 964.64,1402.68
  region net PB14: 1004.35,1548.1 995.63,1529.58 987.02,1540.13 990.73,1548.01
  region net PB14: 1059.04,1542.9 1059.02,1522.43 1071.31,1528.56 1071.32,1536.75
  region net PB15: 956.31,1519.41 936.33,1514.96 953.06,1502.68 964.64,1502.68
  region net PB12: 1059.04,1642.9 1059.02,1622.43 1071.31,1628.56 1071.32,1636.75
  region net PB13: 962.28,1632.39 950.19,1615.88 963.7,1613.54 968.6,1620.22
  region net PD1: 2527.35,617.6 2507.25,613.73 2510.88,626.93 2519.07,628.51
  region net PD0: 2601.62,522.13 2601.62,518.19 2613.91,516.06 2613.91,524.25
  region net PD0: 2572.79,542.55 2558.98,527.44 2554.05,540.25 2559.58,546.31
  region net PB14: 607.72,1641.14 605,1615 630,1627.56 625,1627.56
  region net NetJ1_4: 1673.39,1742.87 1673.39,1782.24 1649.77,1770.43 1649.77,1754.68
  region net PB2: 1775.75,1740.9 1736.39,1740.9 1748.19,1717.28 1763.94,1717.28
  region net BOOT0: 1323.63,1740.9 1284.45,1740.9 1296.47,1717.28 1312.22,1717.28
  region net NetJ1_3: 1386.62,1782.24 1386.62,1742.87 1410.24,1754.68 1410.24,1770.43
  region net NRST: 2639.25,745.17 2639.25,770.17 2624.25,762.76 2624.25,752.76
  region net PA12: 606.65,1300.9 571.18,1300.9 582.99,1277.28 598.74,1277.28
  region net NRST: 2605.56,770.37 2605.56,745.37 2620.56,752.78 2620.56,762.78
  region net VCC: 1387.46,744.91 1372.98,759.39 1368.64,746.36 1374.43,740.57
  region net VCC: 1388.79,778.86 1408.18,785.43 1404.48,797.15 1396.29,794.37
  region net VCC: 1337.5,681.6 1303.79,701.92 1318.19,665.66 1333.93,656.17
  region net VCC: 1352.8,739.21 1367.28,724.73 1371.62,737.76 1365.83,743.55
  region net VCC: 1639.1,1338.27 1628.55,1348.82 1624.21,1335.79 1630,1330
  region net VCC: 1648.56,1390.06 1663.04,1375.58 1667.38,1388.61 1661.59,1394.4
  region net VSSA: 1888.77,804.62 1888.77,829.62 1873.77,822.12 1873.77,812.12
  region net VDDA: 1888.77,875.49 1888.77,900.49 1873.77,892.99 1873.77,882.99
  region net VCC: 1634.13,613.88 1595.37,607 1604.84,584.69 1620.58,587.48
  region net PC14: 1625.86,755.31 1640.37,740.86 1634.06,764.48 1625.88,772.63
  region net PC14: 1662.65,697.45 1644.97,679.77 1660.97,674.56 1668.04,681.63
  region net PC15: 1669.46,795.29 1674.98,792.15 1677.35,787.4 1683.94,780.82 1679.07,783.96 1677.35,787.4
  region net PA12: 571.19,1279.21 610.55,1279.21 598.74,1302.83 582.99,1302.83
  region net PD1: 2525.21,650.9 2504.74,650.9 2510.88,638.62 2519.07,638.62
  region net PC14: 1667.53,657.59 1685.2,675.27 1669.2,680.49 1662.13,673.41
  region net PD0: 2643.72,509.92 2643.72,530.39 2631.43,524.25 2631.43,516.06
  region net VCC: 2346,899.56 2314.2,899.56 2322.22,923.18 2337.97,923.18
  region net PB2: 1765.06,1700.49 1747.06,1700.5 1748.19,1708.9 1763.94,1708.89
  region net BOOT0: 1313.5,1700.58 1295.5,1700.41 1296.55,1708.82 1312.3,1708.96
  region net PA0: 2510.87,1152.59 2510.87,1205.74 2535.67,1184.17 2535.67,1174.17
  region net PA0: 2463.99,1152.59 2463.99,1205.74 2439.19,1183.26 2439.19,1175.07
  region net PA0: 2720.01,1152.59 2720.01,1205.74 2695.2,1184.17 2695.2,1174.17
  region net PA1: 2464.07,1437.3 2463.92,1490.45 2439.18,1467.9 2439.2,1459.71
  region net PA1: 2510.87,1437.37 2510.87,1490.52 2535.67,1468.95 2535.67,1458.95
  region net PA1: 2720.02,1437.37 2720.02,1490.52 2695.21,1468.95 2695.21,1458.95
  region net NetJ1_3: 1459.5,1739.31 1459.5,1785.81 1437.8,1770.43 1437.8,1754.68
  region net NetJ1_4: 1600.5,1739.31 1600.5,1785.81 1622.2,1770.43 1622.2,1754.68
  region net NRST: 2510.87,867.81 2510.87,920.96 2535.67,899.39 2535.67,889.39
  region net NRST: 2720,867.81 2720,920.96 2695.19,899.39 2695.19,889.39
  region net PA14: 1345.46,1042.56 1299.03,1042.56 1290.77,1034.3 1290.77,1034.2 1295.46,1027.56 1300.46,1022.56 1315.46,1022.56 1327.1,1024.2
  region net PA2: 1724.88,1040.92 1765.4,1040.92 1765.44,1040.96 1770.44,1037.56 1740.44,1017.56 1740.44,1025.36
  pour cut-out: 2031.17,832.68 2131.17,832.68 2131.17,732.68 2031.17,732.68
  pour cut-out: 2031.17,1032.68 2131.17,1032.68 2131.17,932.68 2031.17,932.68
  pour cut-out: 1982.79,1582.56 2182.79,1582.56 2182.79,1127.56 1977.79,1132.56
  pour cut-out: 2490.4,627.56 2610.4,627.56 2610.4,487.56 2490.4,487.56
  pour cut-out: 880.44,1682.56 1080.44,1682.56 1080.44,1227.56 875.44,1232.56
  pour cut-out: 880.44,1082.56 1080.44,1077.56 1080.44,627.56 875.44,632.56
  region net NetD1_1: 523.78,465.9 494.26,465.9 496.22,442.28 511.97,442.28
  region net NetD1_1: 484.41,435.11 523.78,435.11 511.97,458.73 496.22,458.73
  region net VCC: 504.32,1777.87 504.32,1817.24 480.69,1805.43 480.69,1789.68
  region net NetLED2_1: 517.33,1745.11 529.69,1723.38 536.08,1742.48 530.95,1751.5
  region net NetLED2_1: 571.82,1775.9 567.3,1800.49 556.38,1776.93 558.58,1764.98
  region net VCC: 504.31,1522.87 504.31,1562.24 480.69,1550.43 480.69,1534.68
  region net NetLED1_1: 567.27,1546.95 585.36,1564.21 569.2,1569.52 561.96,1562.62
  region net NetLED1_1: 526.16,1623.63 513.83,1601.89 532.96,1598.67 532.56,1604.51
  region net VBAT: 1545,661 1571,684 1561.48,685.99 1551.07,687.72 1545.27,681.93
  pour cut-out: 2707.44,2047.24 ccw(c2648.39,2047.24) 2648.39,2106.29 ccw(c2648.39,2047.24) 2589.33,2047.24 ccw(c2648.39,2047.24) 2648.39,1988.18 ccw(c2648.39,2047.24)
  pour cut-out: 2707.44,2047.24 ccw(c2648.39,2047.24) 2648.39,2106.29 ccw(c2648.39,2047.24) 2589.33,2047.24 ccw(c2648.39,2047.24) 2648.39,1988.18 ccw(c2648.39,2047.24)
  pour cut-out: 118.11,324.06 ccw(c118.11,383.12) 177.16,383.12 ccw(c118.11,383.12) 118.11,442.17 ccw(c118.11,383.12) 59.05,383.12 ccw(c118.11,383.12)
  pour cut-out: 118.11,324.06 ccw(c118.11,383.12) 177.16,383.12 ccw(c118.11,383.12) 118.11,442.17 ccw(c118.11,383.12) 59.05,383.12 ccw(c118.11,383.12)
Bottom Layer:
  pour cut-out: -5.06,1337.32 116.78,1337.32 116.78,1619.91 -4.69,1619.91
  region net PA14: 300.5,1006.75 300.5,1053.25 322.2,1034.09 322.2,1025.91
  region net PA10: 310,1746.89 310,1722.91 325.78,1730.81 325.78,1738.99
  region net PA9: 303.01,1811.65 303.01,1858.15 324.71,1838.99 324.71,1830.81
  region net PA13: 300.5,1106.75 300.5,1153.25 322.2,1134.09 322.2,1125.91
  region net BOOT0: 1295.57,1684.62 1313.57,1684.62 1308.66,1676.22 1300.48,1676.22
  region net BOOT0: 956.31,719.41 936.33,714.96 953.06,702.68 964.64,702.68
  region net PA14: 1021.31,1014.96 1001.33,1019.41 993,1002.68 1004.58,1002.68
  region net NRST: 2452.07,896.61 2489.65,859.02 2456.86,856.74 2449.78,863.81
  region net NRST: 2159.47,820.18 2159.47,845.18 2174.47,837.68 2174.47,827.68
  region net PB2: 2000.97,1422.43 2000.95,1442.9 1988.67,1436.75 1988.68,1428.56
  region net PA10: 1001.38,1345.99 1021.37,1350.39 1004.64,1362.68 993.06,1362.68
  region net PA9: 920,1410 909.99,1437.06 910,1450 880,1432.66
  region net PB2: 1765.06,1684.63 1747.06,1684.61 1751.97,1676.22 1760.16,1676.22
  region net PA13: 906.74,1207.56 906.74,1257.76 883.31,1236.75 883.31,1228.56
  pour cut-out: 2712.44,2047.24 ccw(c2648.39,2047.24) 2648.39,2111.29 ccw(c2648.39,2047.24) 2584.33,2047.24 ccw(c2648.39,2047.24) 2648.39,1983.18 ccw(c2648.39,2047.24)
  pour cut-out: 118.11,319.06 ccw(c118.11,383.12) 182.16,383.12 ccw(c118.11,383.12) 118.11,447.17 ccw(c118.11,383.12) 54.05,383.12 ccw(c118.11,383.12)

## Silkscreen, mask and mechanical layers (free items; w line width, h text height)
Top Overlay:
  circle w5: c118.11,118.12 r118.11
  circle w5: c2913.38,118.11 r118.11
  circle w5: c2913.39,2047.24 r118.11
  circle w5: c118.12,2047.25 r118.11
  text "GND" at 120,1880 h35.43
  text "VCC" at 1325.46,1829.84 h35.43
  text "VCC" at 1644.54,1829.84 h35.43
  text "TXD" at 118.94,1809.78 h35.43
  text "BOOT0" at 1100.44,1724.84 h35.43
  text "BOOT1" at 1800.44,1724.84 h35.43
  text "RXD" at 118.94,1709.78 h35.43
  text "GND" at 1325.49,1624.84 h35.43
  text "GND" at 1644.57,1624.84 h35.43
  text "B13" at 655.44,1599.84 h35.43
  text "B12" at 775.44,1599.84 h35.43
  text "VCC" at 2199.57,1594.84 h35.43
  text "GND" at 2314.57,1594.84 h35.43
  text "B15" at 655.44,1499.84 h35.43
  text "B14" at 775.44,1499.84 h35.43
  text "B11" at 2199.57,1494.84 h35.43
  text "B10" at 2314.57,1494.84 h35.43
  text "A9" at 655.44,1399.84 h35.43
  text "A8" at 775.44,1399.84 h35.43
  text "B2" at 2199.57,1394.84 h35.43
  text "B1" at 2314.57,1394.84 h35.43
  text "A11" at 655.44,1299.84 h35.43
  text "A10" at 775.44,1299.84 h35.43
  text "B0" at 2199.57,1294.84 h35.43
  text "A7" at 2314.57,1294.84 h35.43
  text "VCC" at 110,1216.5 h35.43
  text "A13" at 655.44,1199.84 h35.43
  text "A12" at 775.44,1199.84 h35.43
  text "A6" at 2199.57,1194.84 h35.43
  text "A5" at 2314.57,1194.84 h35.43
  text "SWDIO" at 45,1116.5 h35.43
  text "VCC" at 655.44,1099.84 h35.43
  text "GND" at 775.44,1099.84 h35.43
  text "A4" at 2199.57,1094.84 h35.43
  text "A3" at 2314.57,1094.84 h35.43
  text "SWCLK" at 40,1016.5 h35.43
  text "A15" at 655.44,999.84 h35.43
  text "A14" at 775.44,999.84 h35.43
  text "A1" at 2315,999.78 h35.43
  text "A2" at 2199.57,994.84 h35.43
  text "A0" at 2198.94,915 h35.43
  text "VDA" at 2318.94,915 h35.43
  text "GND" at 110,911.5 h35.43
  text "B4" at 655.44,899.84 h35.43
  text "B3" at 775.44,899.84 h35.43
  text "VSA" at 2195,809.78 h35.43
  text "NST" at 2320,809.78 h35.43
  text "B6" at 655.44,799.84 h35.43
  text "B5" at 775.44,799.84 h35.43
  text "RST" at 460,770 h33 r90
  text "BT0" at 655.44,699.84 h35.43
  text "B7" at 775.44,699.84 h35.43
  text "D1" at 2199.57,694.84 h35.43
  text "D0" at 2314.57,694.84 h35.43
  text "GND" at 460,660 h33 r90
  text "B9" at 655.44,599.84 h35.43
  text "B8" at 775.44,599.84 h35.43
  text "C15" at 2199.57,594.84 h35.43
  text "C14" at 2314.57,594.84 h35.43
  text "SDA" at 460,550 h33 r90
  text "VCC" at 655.44,499.84 h35.43
  text "GND" at 775.44,499.84 h35.43
  text "C13" at 2199.57,494.84 h35.43
  text "VCC" at 2314.57,494.84 h35.43
  text "VDD" at 460,440 h33 r90
  text "SCL" at 460,340 h33 r90
  text "MG32F10x series" at 1755.46,190.9 h43.31
  text "EV Board" at 2410.46,190.9 h43.31
  text "LQFP48_V10" at 1755.46,109.7 h43.31
  text "TH226B" at 2370,100 h43.31
Mechanical 1:
  the board outline again, w8.19

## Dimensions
0,0 to 0,2165.35 on Top Overlay
0,0 to 3031.5,0 on Top Overlay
